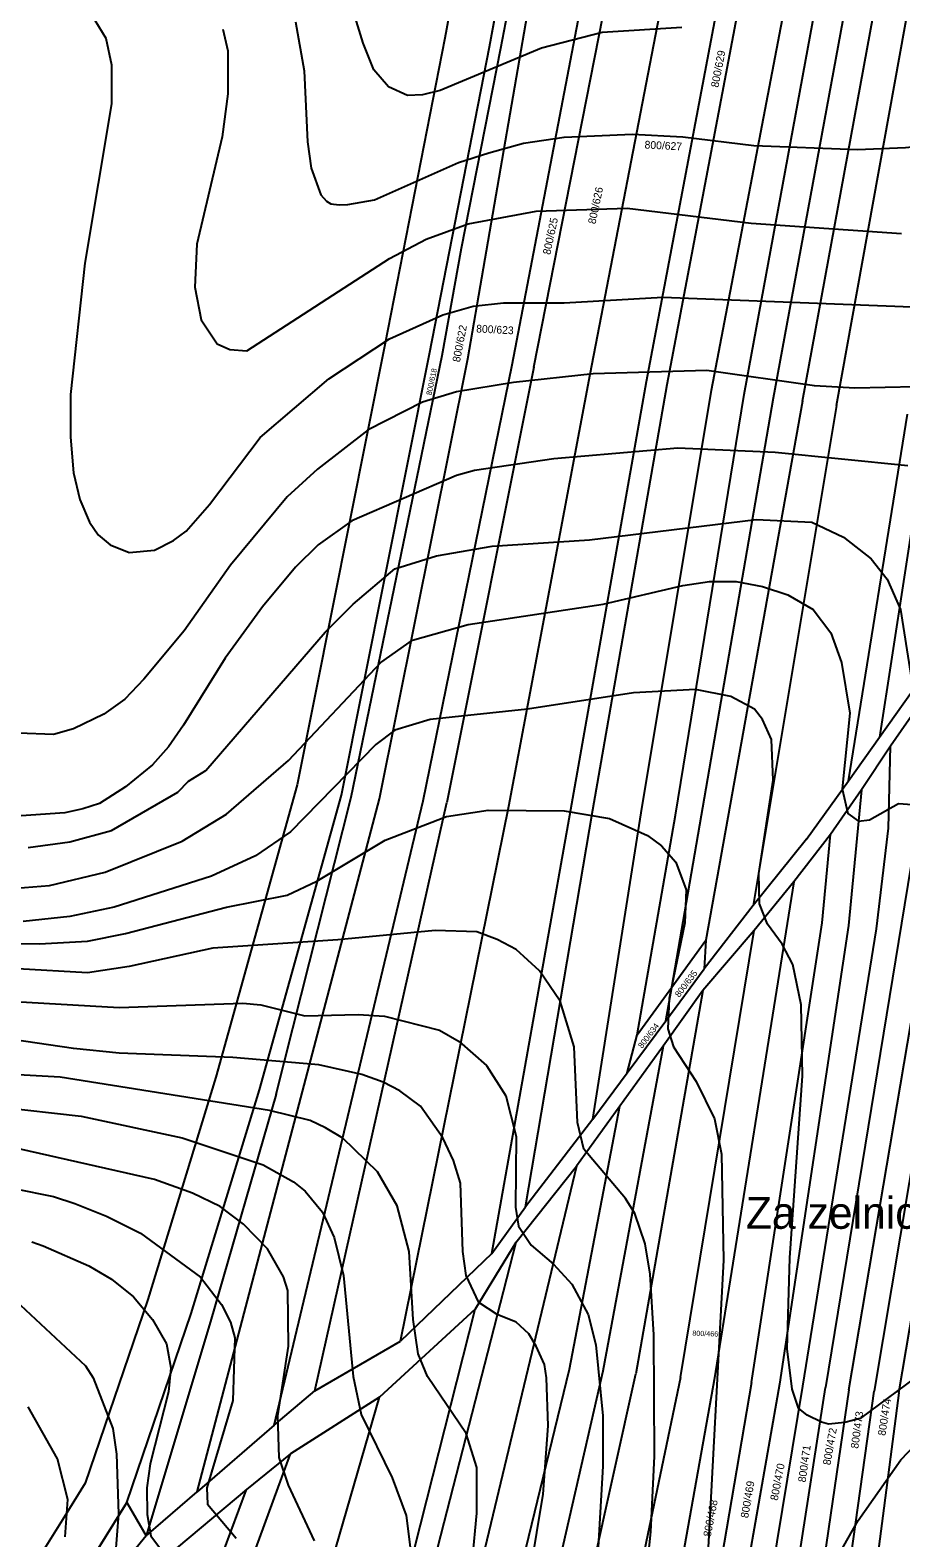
# Model space of a CAD drawing. Extents: x -555860 to -552701, y -1187050 to -1182291.
# Drawn here: x -555242.8 to -555051.8, y -1186105 to -1185774.2 of the extents above; entities that cross this region are included whole.
import ezdxf

# ---------------------------------------------------------------- set-up
doc = ezdxf.new("R2010")
doc.units = 0
for name, color, linetype in [('LEG_2b', 7, 'Continuous'), ('Level 28', 7, 'Continuous'), ('Level 30', 7, 'Continuous'), ('Level 40', 7, 'Continuous'), ('Level 41', 7, 'Continuous'), ('navrh_BV', 7, 'Continuous'), ('Parcelní čísla', 7, 'Continuous')]:
    doc.layers.add(name, color=color, linetype=linetype)

msp = doc.modelspace()

# ---------------------------------------------------------------- linework, layer by layer
at = {"layer": 'Level 28'}
msp.add_lwpolyline([(-555442.31, -1186577.98), (-555406.59, -1186543.53), (-555377.44, -1186522.92), (-555374.35, -1186523.58), (-555365.28, -1186506.04), (-555344.77, -1186450.74), (-555332.46, -1186411.11), (-555310.66, -1186348.84), (-555286.2, -1186267.7), (-555265.72, -1186201.29), (-555264.37, -1186194.41), (-555241.55, -1186134.03), (-555230.94, -1186112.37), (-555227.21, -1186106.32), (-555221.63, -1186097.28), (-555207.51, -1186055.79), (-555192.48, -1186006.73), (-555174.48, -1185942.09), (-555155.23, -1185845.2), (-555142.06, -1185777.85), (-555134.73, -1185738.4)], dxfattribs=at)
at = {"layer": 'Level 30'}
for points in [[(-555144.59, -1185736.72), (-555151.88, -1185775.98), (-555165.04, -1185843.27), (-555184.21, -1185939.77), (-555202.08, -1186003.92), (-555217.03, -1186052.71), (-555230.73, -1186092.99), (-555235.72, -1186101.07), (-555239.71, -1186107.53), (-555250.74, -1186130.05), (-555274.02, -1186191.66), (-555275.43, -1186198.85), (-555295.77, -1186264.78), (-555320.17, -1186345.74), (-555341.96, -1186407.97), (-555354.24, -1186447.52), (-555374.44, -1186501.99), (-555379.79, -1186512.34), (-555412.98, -1186535.8), (-555449.03, -1186570.57), (-555498.13, -1186612.45), (-555503.1, -1186627.13), (-555509.78, -1186661.52), (-555516.07, -1186705.9)], [(-555442.31, -1186577.98), (-555406.59, -1186543.53), (-555377.44, -1186522.92), (-555374.35, -1186523.58), (-555365.28, -1186506.04), (-555344.77, -1186450.74), (-555332.46, -1186411.11), (-555310.66, -1186348.84), (-555286.2, -1186267.7), (-555265.72, -1186201.29), (-555264.37, -1186194.41), (-555241.55, -1186134.03), (-555230.94, -1186112.37), (-555227.21, -1186106.32), (-555221.63, -1186097.28), (-555207.51, -1186055.79), (-555192.48, -1186006.73), (-555174.48, -1185942.09), (-555155.23, -1185845.2), (-555142.06, -1185777.85), (-555134.73, -1185738.4)]]:
    msp.add_lwpolyline(points, dxfattribs=at)
at = {"layer": 'Level 40'}
for points in [[(-555200.56, -1185774.01), (-555199.45, -1185778.73), (-555199.45, -1185788.16), (-555200.69, -1185797.59), (-555206.24, -1185821.16), (-555206.66, -1185830.59), (-555205.27, -1185837.8), (-555201.8, -1185843.06), (-555199.03, -1185844.31), (-555195.29, -1185844.59), (-555163.95, -1185824.34), (-555155.91, -1185820.05), (-555146.76, -1185816.72), (-555131.78, -1185813.95), (-555111.82, -1185813.25), (-555084.64, -1185816.58), (-555051.64, -1185818.8)], [(-555249.64, -1185962.73), (-555238.55, -1185961.89), (-555226.35, -1185958.98), (-555209.43, -1185952.19), (-555199.72, -1185946.23), (-555186.14, -1185934.44), (-555165.89, -1185912.95), (-555158.96, -1185908.09), (-555146.76, -1185904.63), (-555117.08, -1185900.19), (-555099.61, -1185896.03), (-555093.79, -1185895.2), (-555087.97, -1185895.2), (-555082.14, -1185896.31), (-555076.6, -1185898.11), (-555071.05, -1185901.3), (-555067.17, -1185906.43), (-555064.81, -1185912.95), (-555063.01, -1185924.04), (-555064.67, -1185940.68), (-555063.42, -1185946.09), (-555061.07, -1185947.75), (-555058.71, -1185947.47), (-555052.33, -1185943.87), (-555047.34, -1185944.28)], [(-555134.42, -1186120.66), (-555130.26, -1186095.42), (-555129.15, -1186080.45), (-555129.56, -1186069.91), (-555129.99, -1186066.96), (-555131.78, -1186062.97), (-555133.45, -1186060.27), (-555136.22, -1186057.71), (-555140.38, -1186056.04), (-555144.4, -1186053.41), (-555147.17, -1186047.45), (-555147.87, -1186042.18), (-555148.42, -1186027.2), (-555149.95, -1186022.21), (-555152.3, -1186017.22), (-555157.16, -1186010.28), (-555161.69, -1186006.92), (-555165.34, -1186005.02), (-555170.05, -1186003.35), (-555179.48, -1186001.27), (-555198.34, -1185999.61), (-555223.3, -1185998.64), (-555233.28, -1185997.67), (-555268.22, -1185992.54)], [(-555242.43, -1186040.05), (-555239.94, -1186040.93), (-555229.95, -1186045.36), (-555224.96, -1186048.28), (-555220.11, -1186052.16), (-555215.95, -1186057.15), (-555212.9, -1186062.42), (-555211.93, -1186067.69), (-555212.48, -1186072.96), (-555216.5, -1186088.76), (-555217.2, -1186094.03), (-555217.12, -1186099.88), (-555216.36, -1186104.57), (-555208.74, -1186114.83)]]:
    msp.add_lwpolyline(points, dxfattribs=at)
at = {"layer": 'Level 41'}
for points in [[(-555099.89, -1185773.6), (-555117.36, -1185774.71), (-555130.67, -1185778.17), (-555152.86, -1185787.46), (-555156.74, -1185788.43), (-555160.07, -1185788.57), (-555164.23, -1185786.63), (-555167.42, -1185782.89), (-555169.77, -1185777.06), (-555173.93, -1185763.48)], [(-555184.61, -1185772.35), (-555182.67, -1185783.16), (-555181.98, -1185798.7), (-555181.14, -1185804.52), (-555179.06, -1185810.34), (-555177.8, -1185811.75), (-555176.84, -1185812.28), (-555175.04, -1185812.56), (-555173.1, -1185812.49), (-555167.28, -1185811.45), (-555148.84, -1185803.27), (-555142.16, -1185801.11), (-555134.56, -1185798.97), (-555125.68, -1185797.72), (-555110.71, -1185797.03), (-555099.61, -1185797.58), (-555084.08, -1185799.53), (-555061.34, -1185800.36), (-555050.81, -1185799.94), (-555035.28, -1185798.42), (-554970.94, -1185783.86), (-554949.31, -1185778.03), (-554902.72, -1185766.94)], [(-555229.4, -1185770.69), (-555226.21, -1185775.95), (-555224.96, -1185781.78), (-555224.96, -1185790.38), (-555230.78, -1185825.32), (-555233.97, -1185854.16), (-555233.99, -1185863.48), (-555233.28, -1185871.35), (-555231.89, -1185877.18), (-555229.81, -1185882.17), (-555227.87, -1185884.94), (-555225.24, -1185887.16), (-555221.08, -1185888.82), (-555215.53, -1185888.27), (-555211.37, -1185886.19), (-555208.6, -1185884.11), (-555203.47, -1185878.28), (-555192.38, -1185863.59), (-555177.26, -1185850.69), (-555163.95, -1185841.96), (-555152.3, -1185836.69), (-555145.65, -1185834.75), (-555138.99, -1185834.05), (-555125.68, -1185834.05), (-555104.05, -1185832.8), (-555047.48, -1185835.02)], [(-555041.93, -1185852.35), (-555061.9, -1185852.77), (-555070.77, -1185852.22), (-555094.34, -1185848.89), (-555119.3, -1185849.58), (-555136.77, -1185851.52), (-555149.25, -1185853.6), (-555156.74, -1185855.82), (-555168.67, -1185861.92), (-555179.76, -1185870.52), (-555186.41, -1185876.62), (-555198.89, -1185891.59), (-555209.01, -1185906.01), (-555217.88, -1185916.58), (-555222.05, -1185920.99), (-555226.62, -1185924.32), (-555233.28, -1185927.51), (-555237.72, -1185928.76), (-555245.34, -1185928.48)], [(-555050.25, -1185869.82), (-555079.37, -1185866.91), (-555100.72, -1185865.94), (-555127.9, -1185868.3), (-555145.37, -1185870.8), (-555149.25, -1185871.91), (-555172.27, -1185881.89), (-555179.62, -1185887.16), (-555184.61, -1185892.01), (-555191.82, -1185900.75), (-555200, -1185911.98), (-555209.15, -1185926.68), (-555212.44, -1185931.43), (-555215.95, -1185935.41), (-555221.91, -1185940.26), (-555227.59, -1185943.87), (-555231.25, -1185945.05), (-555235.22, -1185945.95), (-555246.87, -1185946.78)], [(-555243.26, -1185953.57), (-555234.11, -1185952.33), (-555224.96, -1185949.83), (-555210.4, -1185941.37), (-555208.04, -1185939.01), (-555204.3, -1185936.66), (-555178.09, -1185906.29), (-555171.99, -1185900.19), (-555162.84, -1185892.43), (-555153.69, -1185889.52), (-555141.49, -1185887.44), (-555120.14, -1185886.05), (-555083.53, -1185881.61), (-555071.33, -1185882.17), (-555064.4, -1185885.49), (-555058.29, -1185890.21), (-555054.83, -1185894.65), (-555051.92, -1185901.3), (-555048.86, -1185920.43)], [(-555046.65, -1186068.38), (-555060.73, -1186078.84), (-555064.12, -1186079.75), (-555067.66, -1186080.07), (-555069.25, -1186079.61), (-555072.36, -1186078.09), (-555074.24, -1186076.56), (-555075.63, -1186072.4), (-555076.73, -1186063.53), (-555076.18, -1186043.56), (-555073.41, -1186003.63), (-555073.69, -1185988.1), (-555075.49, -1185979.23), (-555077.84, -1185974.79), (-555081.03, -1185970.35), (-555082.84, -1185965.91), (-555082.97, -1185959.26), (-555079.79, -1185938.74), (-555080.2, -1185929.86), (-555082.14, -1185925.43), (-555083.95, -1185923.21), (-555089.08, -1185920.43), (-555096.84, -1185918.91), (-555110.43, -1185919.6), (-555133.72, -1185923.21), (-555155.08, -1185925.43), (-555162.84, -1185927.78), (-555167, -1185930.97), (-555185.72, -1185950.11), (-555193.35, -1185955.38), (-555203.05, -1185959.81), (-555224.41, -1185966.61), (-555234.11, -1185968.69), (-555244.37, -1185969.8)], [(-555270.99, -1185974.51), (-555240.77, -1185974.65), (-555230.23, -1185974.1), (-555221.91, -1185972.43), (-555199.72, -1185966.61), (-555186.41, -1185963.97), (-555179.9, -1185960.92), (-555164.92, -1185951.91), (-555151.47, -1185946.78), (-555142.32, -1185945.39), (-555125.68, -1185945.53), (-555115.7, -1185947.2), (-555107.38, -1185950.94), (-555104.33, -1185953.16), (-555101.14, -1185956.76), (-555098.92, -1185962.86), (-555099.2, -1185970.07), (-555102.66, -1185986.71), (-555102.94, -1185993.37), (-555101.69, -1185997.25), (-555096.7, -1186004.88), (-555092.68, -1186013.06), (-555091.16, -1186020.82), (-555090.74, -1186044.12), (-555094.48, -1186114)], [(-555108.35, -1186120.1), (-555106.69, -1186103.74), (-555105.85, -1186087.1), (-555105.99, -1186060.48), (-555106.82, -1186047.17), (-555107.93, -1186040.51), (-555110.15, -1186033.86), (-555112.23, -1186030.53), (-555121.38, -1186019.71), (-555122.77, -1186013.89), (-555123.46, -1185997.25), (-555126.51, -1185987.27), (-555131.09, -1185980.61), (-555136.22, -1185975.9), (-555140.4, -1185973.76), (-555144.82, -1185972.02), (-555153.97, -1185971.74), (-555175.32, -1185973.82), (-555202.77, -1185975.62), (-555221.08, -1185979.64), (-555230.23, -1185981.03), (-555245.48, -1185980.2)], [(-555260.18, -1185986.57), (-555223.3, -1185988.66), (-555196.12, -1185987.68), (-555192.24, -1185988.1), (-555182.53, -1185990.46), (-555170.88, -1185990.18), (-555165.06, -1185990.59), (-555153, -1185993.65), (-555148.7, -1185996.14), (-555142.74, -1186001.41), (-555138.44, -1186008.07), (-555136.22, -1186016.94), (-555136.36, -1186032.47), (-555135.66, -1186036.63), (-555132.89, -1186040.79), (-555128.04, -1186044.95), (-555124.02, -1186049.39), (-555120.41, -1186056.04), (-555118.75, -1186062.7), (-555117.22, -1186078.23), (-555117.22, -1186089.32), (-555118.19, -1186107.07)], [(-555146.76, -1186119.82), (-555144.82, -1186099.58), (-555144.82, -1186089.6), (-555147.17, -1186082.11), (-555155.63, -1186069.63), (-555157.71, -1186064.64), (-555158.82, -1186057.15), (-555159.65, -1186042.18), (-555162.29, -1186032.19), (-555166.58, -1186024.71), (-555174.21, -1186017.36), (-555178.03, -1186015.09), (-555181.42, -1186013.47), (-555190.3, -1186011.26), (-555236.2, -1186003.95), (-555254.63, -1186002.94)], [(-555249.92, -1186010.42), (-555231.61, -1186012.5), (-555209.43, -1186017.22), (-555191.68, -1186023.18), (-555185.03, -1186026.92), (-555182.48, -1186028.95), (-555178.65, -1186033.58), (-555176.15, -1186039.13), (-555174.07, -1186047.45), (-555171.99, -1186069.63), (-555170.19, -1186077.95), (-555163.4, -1186091.82), (-555160.34, -1186100.13), (-555158.54, -1186114)], [(-555180.45, -1186105.68), (-555186.14, -1186093.48), (-555188.21, -1186087.38), (-555188.49, -1186078.23), (-555186.14, -1186062.97), (-555186.27, -1186050.77), (-555187.24, -1186047.72), (-555190.71, -1186041.62), (-555195.98, -1186036.21), (-555201.11, -1186032.33), (-555207.21, -1186029.42), (-555215.53, -1186026.37), (-555259.9, -1186016.39)], [(-555255.19, -1186026.65), (-555237.72, -1186030.11), (-555232.98, -1186031.68), (-555226.07, -1186034.41), (-555218.58, -1186038.16), (-555205.41, -1186047.86), (-555200.83, -1186053.82), (-555198.89, -1186057.71), (-555197.92, -1186061.17), (-555198.34, -1186074.9), (-555204.02, -1186094.03), (-555203.88, -1186097.64), (-555197.64, -1186105.13)], [(-555068.69, -1186114.55), (-555061.2, -1186101.24), (-555051.78, -1186087.93), (-555043.6, -1186079.34), (-555038.6, -1186075.59), (-555033.34, -1186073.1), (-555027.23, -1186071.16), (-554985.08, -1186063.67), (-554958.46, -1186056.87), (-554943.76, -1186049.8), (-554931.28, -1186039.4), (-554924.49, -1186035.66), (-554918.25, -1186034.41), (-554911.04, -1186034.97), (-554904.39, -1186038.99), (-554901.2, -1186041.76), (-554898.28, -1186045.36), (-554881.51, -1186071.29), (-554873.74, -1186084.88), (-554867.92, -1186100.41), (-554865.98, -1186108.18)], [(-555244.93, -1186053.96), (-555230.64, -1186067.27), (-555229, -1186069.93), (-555224.68, -1186081), (-555223.85, -1186086.68), (-555223.4, -1186099.77), (-555224.15, -1186109.1)], [(-555235.14, -1186104.81), (-555234.58, -1186096.6), (-555236.82, -1186087.65), (-555243.26, -1186076.28)]]:
    msp.add_lwpolyline(points, dxfattribs=at)
at = {"layer": 'navrh_BV'}
for p, q in [((-555146.81, -1185846.35), (-555109.6, -1185630.41)), ((-555142.06, -1185777.85), (-555134.73, -1185738.4)), ((-555139.57, -1185778.14), (-555131.98, -1185738.91)), ((-555137.1, -1185847.63), (-555116.56, -1185740.62)), ((-555132.33, -1185848.15), (-555111.31, -1185741.2)), ((-555119.95, -1185849.7), (-555099.3, -1185742.61)), ((-555107.61, -1185851.32), (-555087.26, -1185743.94)), ((-555103.08, -1185851.98), (-555082.7, -1185744.45)), ((-555093.32, -1185853.2), (-555072.82, -1185745.55)), ((-555086.16, -1185854.14), (-555066.29, -1185746.1)), ((-555079.75, -1185854.89), (-555059.87, -1185746.68)), ((-555073.42, -1185855.6), (-555053.52, -1185747.28)), ((-555065.93, -1185856.6), (-555046.39, -1185748.29)), ((-555155.23, -1185845.2), (-555142.06, -1185777.85)), ((-555148.18, -1185822.03), (-555139.57, -1185778.14)), ((-555152.44, -1185845.56), (-555148.18, -1185822.03)), ((-555174.48, -1185942.09), (-555155.23, -1185845.2)), ((-555172.42, -1185942.53), (-555152.44, -1185845.56)), ((-555166.2, -1185942.88), (-555146.81, -1185846.35)), ((-555156.57, -1185943.29), (-555137.1, -1185847.63)), ((-555132.33, -1185848.15), (-555151.43, -1185943.69)), ((-555137.83, -1185944.49), (-555119.95, -1185849.7)), ((-555124.21, -1185945.19), (-555107.61, -1185851.32)), ((-555119.41, -1185945.31), (-555103.08, -1185851.98)), ((-555108.75, -1185945.91), (-555093.32, -1185853.2)), ((-555102.08, -1185984.22), (-555079.75, -1185854.89)), ((-555101.24, -1185946.45), (-555086.16, -1185854.14)), ((-555073.42, -1185855.6), (-555094.56, -1185973.86)), ((-555065.93, -1185856.6), (-555084.21, -1185966.25)), ((-555063.31, -1185938.92), (-555050.39, -1185858.49)), ((-555045.67, -1185859.13), (-555056.48, -1185929.31)), ((-555056.48, -1185929.31), (-555049.33, -1185919.22)), ((-555047.71, -1185922.2), (-555054.07, -1185931.3)), ((-555063.31, -1185938.92), (-555056.48, -1185929.31)), ((-555054.07, -1185931.3), (-555060.44, -1185940.89)), ((-555054.51, -1185949.31), (-555054.07, -1185931.3)), ((-555072.5, -1185951.73), (-555063.31, -1185938.92)), ((-555060.44, -1185940.89), (-555067.22, -1185950.68)), ((-555060.44, -1185940.89), (-555063.26, -1185970.67)), ((-555206.21, -1186094.96), (-555166.2, -1185942.88)), ((-555192.48, -1186006.73), (-555174.48, -1185942.09)), ((-555189.25, -1186080.31), (-555156.57, -1185943.29)), ((-555188.84, -1186007.65), (-555172.42, -1185942.53)), ((-555180.37, -1186072.76), (-555151.43, -1185943.69)), ((-555161.59, -1186061.84), (-555137.83, -1185944.49)), ((-555141.56, -1186042.66), (-555124.21, -1185945.19)), ((-555134.16, -1186032.41), (-555119.41, -1185945.31)), ((-555119.38, -1186013.15), (-555108.75, -1185945.91)), ((-555109.69, -1185994.67), (-555101.24, -1185946.45)), ((-555067.22, -1185950.68), (-555075.27, -1185961.05)), ((-555069.05, -1185970.08), (-555067.22, -1185950.68)), ((-555048.34, -1185949.57), (-555068.31, -1186072.02)), ((-555063.2, -1186072.55), (-555042.48, -1185949.81)), ((-555037.18, -1185950.35), (-555057.66, -1186072.82)), ((-555057.16, -1185971.43), (-555054.51, -1185949.31)), ((-555052.27, -1186073.22), (-555031.59, -1185950.56)), ((-555072.5, -1185951.73), (-555084.21, -1185966.25)), ((-555075.27, -1185961.05), (-555092.74, -1186070.37)), ((-555075.27, -1185961.05), (-555084.02, -1185971.77)), ((-555084.21, -1185966.25), (-555094.93, -1185980.16)), ((-555084.56, -1186070.95), (-555069.05, -1185970.08)), ((-555063.26, -1185970.67), (-555078.41, -1186071.33)), ((-555102.08, -1185984.22), (-555094.56, -1185973.86)), ((-555100.12, -1186069.85), (-555084.02, -1185971.77)), ((-555084.02, -1185971.77), (-555095.22, -1185984.91)), ((-555094.56, -1185973.86), (-555094.93, -1185980.16)), ((-555073.34, -1186071.77), (-555057.16, -1185971.43)), ((-555103.37, -1185991.56), (-555094.93, -1185980.16)), ((-555095.22, -1185984.91), (-555109.93, -1186069.02)), ((-555109.69, -1185994.67), (-555102.08, -1185984.22)), ((-555095.22, -1185984.91), (-555103.97, -1185997.13)), ((-555103.37, -1185991.56), (-555102.08, -1185984.22)), ((-555111.82, -1186002.96), (-555103.37, -1185991.56)), ((-555103.97, -1185997.13), (-555117.16, -1186068.44)), ((-555103.97, -1185997.13), (-555113.44, -1186010.28)), ((-555111.82, -1186002.96), (-555109.69, -1185994.67)), ((-555119.38, -1186013.15), (-555111.82, -1186002.96)), ((-555199.74, -1186030.43), (-555192.48, -1186006.73)), ((-555188.84, -1186007.65), (-555203.25, -1186057.58)), ((-555124.49, -1186067.99), (-555113.44, -1186010.28)), ((-555113.44, -1186010.28), (-555122.97, -1186023.5)), ((-555119.38, -1186013.15), (-555134.16, -1186032.41)), ((-555122.97, -1186023.5), (-555153.54, -1186150.9)), ((-555136.26, -1186040.23), (-555122.97, -1186023.5)), ((-555207.51, -1186055.79), (-555199.74, -1186030.43)), ((-555141.56, -1186042.66), (-555134.16, -1186032.41)), ((-555136.26, -1186040.23), (-555164.18, -1186148.84)), ((-555136.26, -1186040.23), (-555145.21, -1186054.86)), ((-555141.56, -1186042.66), (-555161.59, -1186061.84)), ((-555221.63, -1186097.28), (-555207.51, -1186055.79)), ((-555168.8, -1186148.11), (-555145.21, -1186054.86)), ((-555145.21, -1186054.86), (-555166.19, -1186074.17)), ((-555203.25, -1186057.58), (-555217.36, -1186104.58)), ((-555180.37, -1186072.76), (-555161.59, -1186061.84)), ((-555145.01, -1186152.38), (-555124.49, -1186067.99)), ((-555117.16, -1186068.44), (-555136.65, -1186153.61)), ((-555128.98, -1186154.84), (-555109.93, -1186069.02)), ((-555100.12, -1186069.85), (-555118.35, -1186156.47)), ((-555189.25, -1186080.31), (-555180.37, -1186072.76)), ((-555092.74, -1186070.37), (-555107.3, -1186151.46)), ((-555084.56, -1186070.95), (-555099.78, -1186159.84)), ((-555078.41, -1186071.33), (-555094.23, -1186160.72)), ((-555088.1, -1186161.63), (-555073.34, -1186071.77)), ((-555082.47, -1186162.74), (-555068.31, -1186072.02)), ((-555063.2, -1186072.55), (-555076.56, -1186163.78)), ((-555070.51, -1186164.87), (-555057.66, -1186072.82)), ((-555052.27, -1186073.22), (-555064.25, -1186165.76)), ((-555186.79, -1186145.19), (-555166.19, -1186074.17)), ((-555166.19, -1186074.17), (-555185.67, -1186086.62)), ((-555189.25, -1186080.31), (-555206.21, -1186094.96)), ((-555230.2, -1186207.64), (-555185.67, -1186086.62)), ((-555185.67, -1186086.62), (-555195.33, -1186094.42)), ((-555236.71, -1186204.91), (-555195.33, -1186094.42)), ((-555217.36, -1186104.58), (-555206.21, -1186094.96)), ((-555195.33, -1186094.42), (-555212.97, -1186109.19)), ((-555221.63, -1186097.28), (-555230.94, -1186112.37)), ((-555221.63, -1186097.28), (-555217.36, -1186104.58)), ((-555217.36, -1186104.58), (-555226.45, -1186115.68))]:
    msp.add_line(p, q, dxfattribs=at)

# ---------------------------------------------------------------- texts
at = {"layer": 'LEG_2b'}
for s, height, rotation, p in [('800/629', 1.7, 79, (-555091.84, -1185786.9)), ('800/627', 1.7, 357, (-555108.06, -1185800.16)), ('800/626', 1.7, 78, (-555118.81, -1185816.86)), ('800/625', 1.7, 78, (-555128.72, -1185823.59)), ('800/622', 1.7, 79, (-555148.55, -1185847.16)), ('800/623', 1.7, 357, (-555145, -1185840.52)), ('800/618', 1.2, 78, (-555154.78, -1185854.41)), ('800/635', 1.4, 53, (-555100.4, -1185986.54)), ('800/634', 1.3, 53, (-555108.54, -1185997.74)), ('800/466', 1.139, 358, (-555097.57, -1186060.67)), ('800/474', 1.7, 81, (-555055.22, -1186082.71)), ('800/473', 1.7, 82, (-555061.16, -1186085.53)), ('800/472', 1.7, 80, (-555067.27, -1186089.16)), ('800/471', 1.7, 82, (-555072.71, -1186092.92)), ('800/470', 1.7, 79, (-555078.83, -1186096.95)), ('800/469', 1.7, 80, (-555085.32, -1186100.79)), ('800/468', 1.7, 79, (-555093.52, -1186104.91))]:
    msp.add_text(s, height=height, rotation=rotation, dxfattribs=at).set_placement(p)
at = {"layer": 'Parcelní čísla'}
msp.add_text('Za zelnicemi', height=7, dxfattribs=at).set_placement((-555085.82, -1186037.21))

doc.saveas('drawing.dxf')
